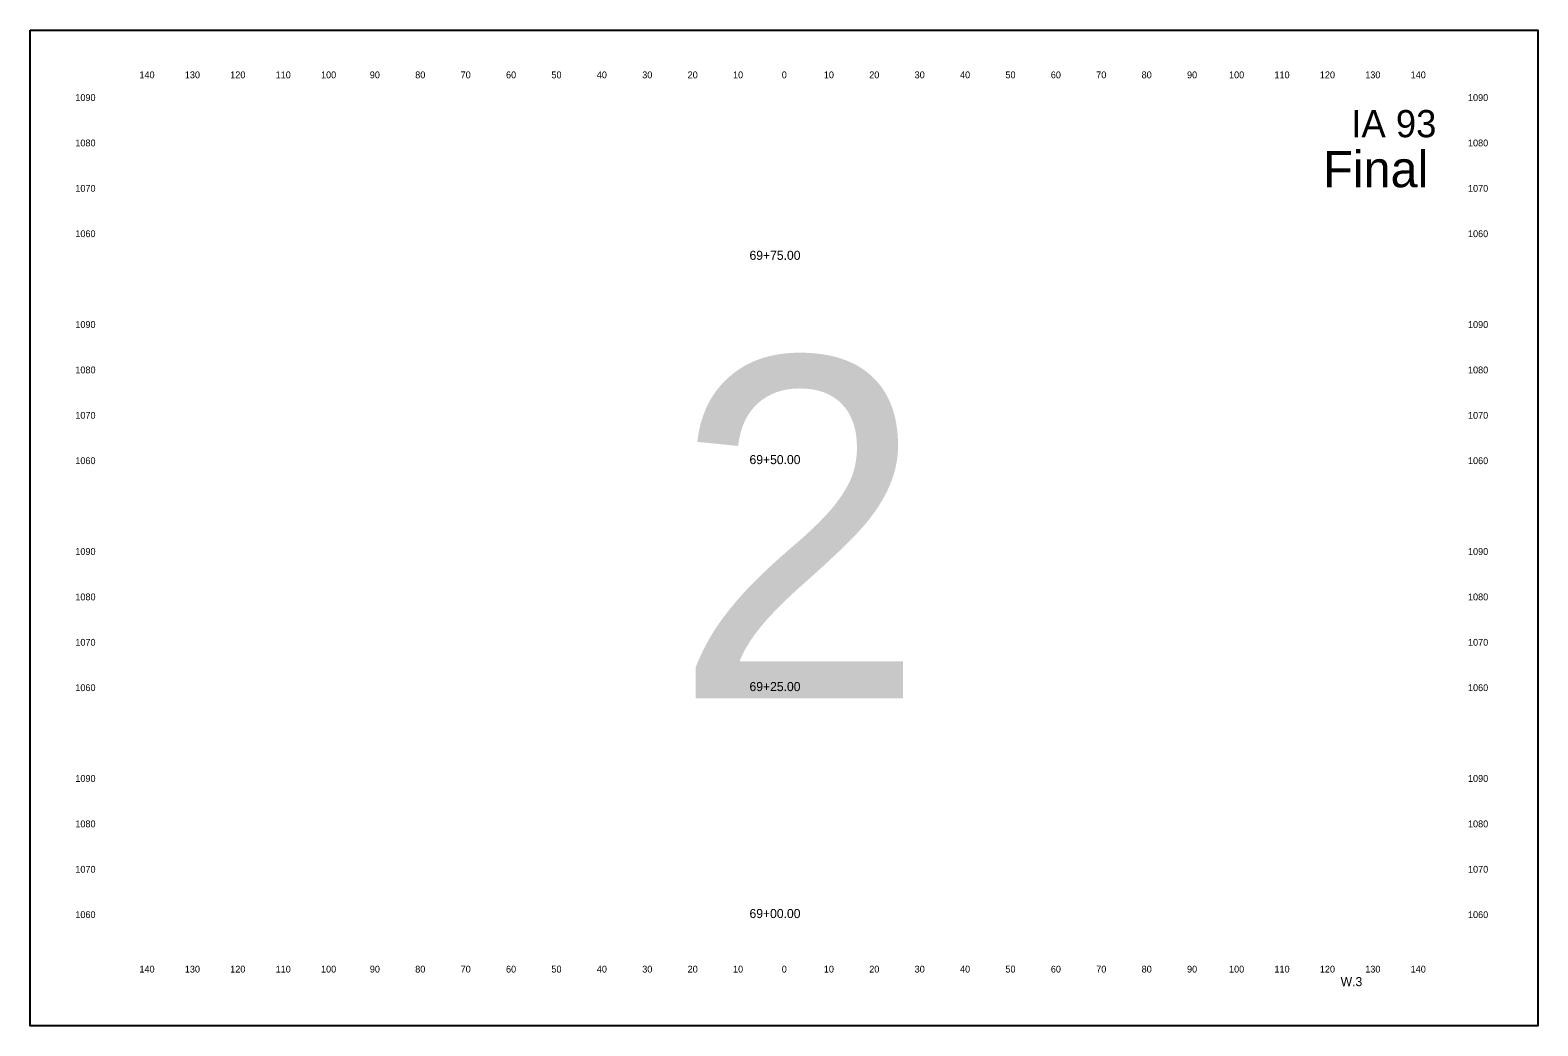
# Model space of a CAD drawing. Extents: x 10123 to 11535, y 9730 to 9950.
# Drawn here: x 10483.2 to 10815.3, y 9730.3 to 9949.6 of the extents above; entities that cross this region are included whole.
import ezdxf

# ---------------------------------------------------------------- set-up
doc = ezdxf.new("R2010")
doc.units = 0
for name, color, linetype in [('dsn3DSubgradeHingePoint', 7, 'Continuous'), ('dsnXSEarthwork', 7, 'Continuous'), ('dsnXsPCCPavement', 7, 'Continuous'), ('dsnXsShldrEarthFill', 7, 'Continuous')]:
    doc.layers.add(name, color=color, linetype=linetype)

msp = doc.modelspace()

# ---------------------------------------------------------------- linework, layer by layer
at = {"layer": 'dsnXsShldrEarthFill'}
msp.add_lwpolyline([(10483.21, 9949.6), (10815.29, 9949.6), (10815.29, 9730.26), (10483.21, 9730.26)], close=True, dxfattribs=at)

# ---------------------------------------------------------------- texts
at = {"layer": 'dsn3DSubgradeHingePoint'}
for s, height, p in [('140', 1.5, (10507.27, 9939)), ('130', 1.5, (10517.27, 9939)), ('120', 1.5, (10527.27, 9939)), ('110', 1.5, (10537.27, 9939)), ('100', 1.5, (10547.27, 9939)), ('90', 1.5, (10558.02, 9939)), ('80', 1.5, (10568.02, 9939)), ('70', 1.5, (10578.02, 9939)), ('60', 1.5, (10588.02, 9939)), ('50', 1.5, (10598.02, 9939)), ('40', 1.5, (10608.02, 9939)), ('30', 1.5, (10618.02, 9939)), ('20', 1.5, (10628.02, 9939)), ('10', 1.5, (10638.02, 9939)), ('0', 1.5, (10648.76, 9939)), ('0', 1.5, (10648.76, 9939)), ('10', 1.5, (10658.02, 9939)), ('20', 1.5, (10668.02, 9939)), ('30', 1.5, (10678.02, 9939)), ('40', 1.5, (10688.02, 9939)), ('50', 1.5, (10698.02, 9939)), ('60', 1.5, (10708.02, 9939)), ('70', 1.5, (10718.02, 9939)), ('80', 1.5, (10728.02, 9939)), ('90', 1.5, (10738.02, 9939)), ('100', 1.5, (10747.27, 9939)), ('110', 1.5, (10757.27, 9939)), ('120', 1.5, (10767.27, 9939)), ('130', 1.5, (10777.27, 9939)), ('140', 1.5, (10787.27, 9939)), ('1090', 1.5, (10493.15, 9934)), ('1090', 1.5, (10799.9, 9934)), ('IA 93', 6, (10774.21, 9926)), ('1080', 1.5, (10493.15, 9924)), ('1080', 1.5, (10799.9, 9924)), ('1070', 1.5, (10493.15, 9914)), ('1070', 1.5, (10799.9, 9914)), ('1060', 1.5, (10493.15, 9904)), ('1060', 1.5, (10799.9, 9904)), ('69+75.00', 2, (10641.65, 9899)), ('1090', 1.5, (10493.15, 9884)), ('1090', 1.5, (10799.9, 9884)), ('1080', 1.5, (10493.15, 9874)), ('1080', 1.5, (10799.9, 9874)), ('1070', 1.5, (10493.15, 9864)), ('1070', 1.5, (10799.9, 9864)), ('1060', 1.5, (10493.15, 9854)), ('69+50.00', 2, (10641.65, 9854)), ('1060', 1.5, (10799.9, 9854)), ('1090', 1.5, (10493.15, 9834)), ('1090', 1.5, (10799.9, 9834)), ('1080', 1.5, (10493.15, 9824)), ('1080', 1.5, (10799.9, 9824)), ('1070', 1.5, (10493.15, 9814)), ('1070', 1.5, (10799.9, 9814)), ('1060', 1.5, (10493.15, 9804)), ('69+25.00', 2, (10641.65, 9804)), ('1060', 1.5, (10799.9, 9804)), ('1090', 1.5, (10493.15, 9784)), ('1090', 1.5, (10799.9, 9784)), ('1080', 1.5, (10493.15, 9774)), ('1080', 1.5, (10799.9, 9774)), ('1070', 1.5, (10493.15, 9764)), ('1070', 1.5, (10799.9, 9764)), ('1060', 1.5, (10493.15, 9754)), ('69+00.00', 2, (10641.65, 9754)), ('1060', 1.5, (10799.9, 9754)), ('140', 1.5, (10507.27, 9742)), ('130', 1.5, (10517.27, 9742)), ('120', 1.5, (10527.27, 9742)), ('110', 1.5, (10537.27, 9742)), ('100', 1.5, (10547.27, 9742)), ('90', 1.5, (10558.02, 9742)), ('80', 1.5, (10568.02, 9742)), ('70', 1.5, (10578.02, 9742)), ('60', 1.5, (10588.02, 9742)), ('50', 1.5, (10598.02, 9742)), ('40', 1.5, (10608.02, 9742)), ('30', 1.5, (10618.02, 9742)), ('20', 1.5, (10628.02, 9742)), ('10', 1.5, (10638.02, 9742)), ('0', 1.5, (10648.76, 9742)), ('0', 1.5, (10648.76, 9742)), ('10', 1.5, (10658.02, 9742)), ('20', 1.5, (10668.02, 9742)), ('30', 1.5, (10678.02, 9742)), ('40', 1.5, (10688.02, 9742)), ('50', 1.5, (10698.02, 9742)), ('60', 1.5, (10708.02, 9742)), ('70', 1.5, (10718.02, 9742)), ('80', 1.5, (10728.02, 9742)), ('90', 1.5, (10738.02, 9742)), ('100', 1.5, (10747.27, 9742)), ('110', 1.5, (10757.27, 9742)), ('120', 1.5, (10767.27, 9742)), ('130', 1.5, (10777.27, 9742)), ('140', 1.5, (10787.27, 9742))]:
    msp.add_text(s, height=height, dxfattribs=at).set_placement(p)
at = {"layer": 'dsnXSEarthwork'}
msp.add_text('Final', height=8, dxfattribs=at).set_placement((10768, 9915))
at = {"layer": 'dsnXsPCCPavement'}
msp.add_text('W.3', height=2, dxfattribs=at).set_placement((10771.86, 9739))
at = {"layer": 'dsnXsShldrEarthFill'}
msp.add_text('2', height=75, dxfattribs=at).set_placement((10624.72, 9802.43))

doc.saveas('drawing.dxf')
